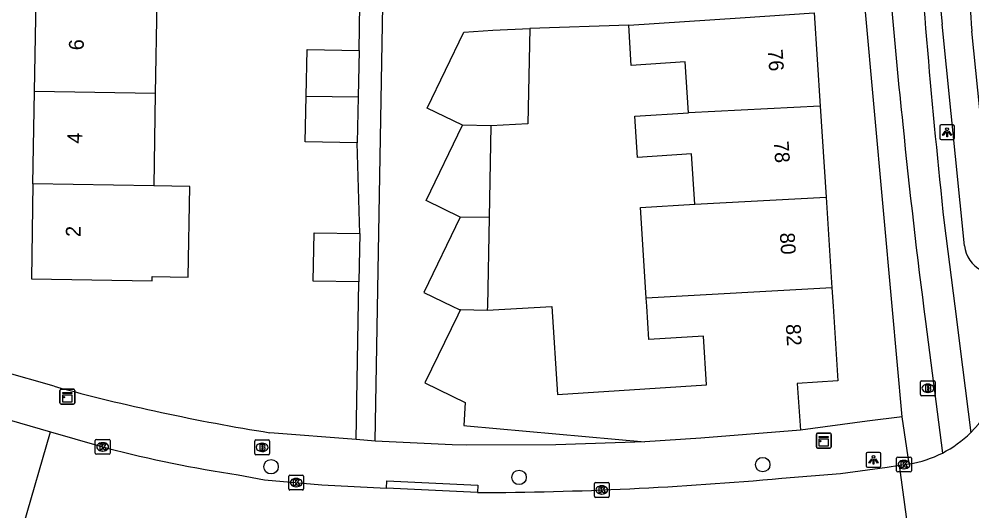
# Model space of a CAD drawing. Extents: x 160026 to 161302, y 384757 to 385701.
# Drawn here: x 160741.7 to 160806.2, y 384986.1 to 385019.4 of the extents above; entities that cross this region are included whole.
import ezdxf

# ---------------------------------------------------------------- set-up
doc = ezdxf.new("R2010")
doc.units = 0
for name, color, linetype in [('IMGEO_Boom', 7, 'Continuous'), ('IMGEO_Brandkraan', 7, 'Continuous'), ('IMGEO_Fietspad_open', 7, 'Continuous'), ('IMGEO_Kast', 7, 'Continuous'), ('IMGEO_Kolk', 7, 'Continuous'), ('IMGEO_Lichtpunt', 7, 'Continuous'), ('IMGEO_Pand', 7, 'Continuous'), ('IMGEO_Pand_nummerreeks', 7, 'Continuous'), ('IMGEO_Parkeervlak_open', 7, 'Continuous'), ('IMGEO_Rijbaan_lokaal_gesloten', 7, 'Continuous'), ('IMGEO_Rijbaan_lokaal_open', 7, 'Continuous'), ('IMGEO_Voetpad_open', 7, 'Continuous')]:
    doc.layers.add(name, color=color, linetype=linetype)

msp = doc.modelspace()

# ---------------------------------------------------------------- linework, layer by layer
at = {"layer": 'IMGEO_Boom'}
for centre in [(160758.765, 384989.14), (160792.032, 384989.282), (160775.542, 384988.414)]:
    msp.add_circle(centre, 0.489, dxfattribs=at)
at = {"layer": 'IMGEO_Brandkraan'}
for p, q in [((160802.703, 384994.017), (160802.703, 384994.869)), ((160802.778, 384994.943), (160803.63, 384994.943)), ((160803.704, 384994.869), (160803.704, 384994.017)), ((160803.214, 384994.163), (160803.189, 384994.163)), ((160803.191, 384994.723), (160803.216, 384994.723)), ((160803.63, 384993.943), (160802.778, 384993.943)), ((160757.734, 384990.949), (160758.586, 384990.949)), ((160757.659, 384990.023), (160757.659, 384990.875)), ((160758.147, 384990.729), (160758.172, 384990.729)), ((160758.66, 384990.875), (160758.66, 384990.023)), ((160758.586, 384989.949), (160757.734, 384989.949)), ((160758.17, 384990.169), (160758.145, 384990.169))]:
    msp.add_line(p, q, dxfattribs=at)
for points in [[(160802.703, 384994.017), (160802.703, 384994.869)], [(160802.778, 384994.943), (160803.63, 384994.943)], [(160803.704, 384994.869), (160803.704, 384994.017)], [(160803.051, 384994.643), (160803.051, 384994.243), (160803.264, 384994.243)], [(160803.282, 384994.643), (160803.051, 384994.643)], [(160803.23, 384994.562), (160803.176, 384994.562), (160803.176, 384994.486)], [(160803.176, 384994.486), (160803.229, 384994.486)], [(160803.238, 384994.41), (160803.176, 384994.41), (160803.176, 384994.329)], [(160803.176, 384994.329), (160803.238, 384994.329)], [(160803.63, 384993.943), (160802.778, 384993.943)], [(160757.734, 384990.949), (160758.586, 384990.949)], [(160757.659, 384990.023), (160757.659, 384990.875)], [(160758.007, 384990.649), (160758.007, 384990.249), (160758.22, 384990.249)], [(160758.238, 384990.649), (160758.007, 384990.649)], [(160758.186, 384990.568), (160758.132, 384990.568), (160758.132, 384990.492)], [(160758.132, 384990.492), (160758.185, 384990.492)], [(160758.194, 384990.416), (160758.132, 384990.416), (160758.132, 384990.335)], [(160758.132, 384990.335), (160758.194, 384990.335)], [(160758.66, 384990.875), (160758.66, 384990.023)], [(160758.586, 384989.949), (160757.734, 384989.949)]]:
    msp.add_lwpolyline(points, dxfattribs=at)
for centre, radius, start, end in [((160802.78, 384994.867), 0.0765, 91.55205, 178.44795), ((160802.78, 384994.867), 0.0765, 91.55205, 178.44795), ((160803.628, 384994.867), 0.0765, 1.55205, 88.44795), ((160803.628, 384994.867), 0.0765, 1.55205, 88.44795), ((160803.231, 384994.524), 0.0379, 267.82845, 90.93552), ((160803.239, 384994.369), 0.0404, 269.87594, 90.50774), ((160803.27, 384994.494), 0.251, 268.66757, 293.53466), ((160803.286, 384994.498), 0.145, 59.4692, 91.53667), ((160803.311, 384994.545), 0.0922, 285.51372, 58.15012), ((160803.316, 384994.353), 0.105, 301.31148, 78.98903), ((160802.78, 384994.019), 0.0765, 181.55205, 268.44795), ((160802.78, 384994.019), 0.0765, 181.55205, 268.44795), ((160803.628, 384994.019), 0.0765, 271.55205, 358.44795), ((160803.628, 384994.019), 0.0765, 271.55205, 358.44795), ((160757.736, 384990.873), 0.0765, 91.55205, 178.44795), ((160757.736, 384990.873), 0.0765, 91.55205, 178.44795), ((160758.584, 384990.873), 0.0765, 1.55205, 88.44795), ((160758.584, 384990.873), 0.0765, 1.55205, 88.44795), ((160758.187, 384990.53), 0.0379, 267.82845, 90.93552), ((160758.195, 384990.375), 0.0404, 269.87594, 90.50774), ((160758.226, 384990.5), 0.251, 268.66757, 293.53466), ((160758.242, 384990.504), 0.145, 59.4692, 91.53667), ((160758.267, 384990.551), 0.0922, 285.51372, 58.15012), ((160758.272, 384990.359), 0.105, 301.31148, 78.98903), ((160757.736, 384990.025), 0.0765, 181.55205, 268.44795), ((160757.736, 384990.025), 0.0765, 181.55205, 268.44795), ((160758.584, 384990.025), 0.0765, 271.55205, 358.44795), ((160758.584, 384990.025), 0.0765, 271.55205, 358.44795)]:
    msp.add_arc(centre, radius, start, end, dxfattribs=at)
for centre, major_axis, ratio, start_param, end_param in [((160803.19, 384994.443), (-0.387, 0.002), 0.722429, 4.712389, 7.853982), ((160803.215, 384994.443), (-0.39, 0.002), 0.717154, 1.570796, 4.712389), ((160758.146, 384990.449), (-0.387, 0.002), 0.722429, 4.712389, 7.853982), ((160758.171, 384990.449), (-0.39, 0.002), 0.717154, 1.570796, 4.712389)]:
    msp.add_ellipse(centre, major_axis=major_axis, ratio=ratio, start_param=start_param, end_param=end_param, dxfattribs=at)
at = {"layer": 'IMGEO_Fietspad_open'}
for points in [[(160804.304, 385005.644), (160804.667, 385002.822), (160805.027, 385000), (160805.547, 384995.863), (160806.104, 384991.441)], [(160803.05, 384998.952), (160804.185, 384990.065)]]:
    msp.add_lwpolyline(points, dxfattribs=at)
for centre, radius, start, end in [((161342.173, 385063.589), 540.981, 183.66637, 186.14879), ((161161.658, 385051.094), 362.235, 183.61885, 186.14936), ((161234.557, 385055.626), 435.213, 185.71448, 187.48234)]:
    msp.add_arc(centre, radius, start, end, dxfattribs=at)
at = {"layer": 'IMGEO_Kast'}
for p, q in [((160744.483, 384993.454), (160744.483, 384994.295)), ((160744.483, 384994.295), (160744.483, 384993.454)), ((160744.558, 384994.379), (160745.399, 384994.379)), ((160745.399, 384994.379), (160744.558, 384994.379)), ((160745.483, 384994.304), (160745.483, 384993.463)), ((160745.483, 384993.463), (160745.483, 384994.304)), ((160745.408, 384993.379), (160744.567, 384993.379)), ((160744.567, 384993.379), (160745.408, 384993.379)), ((160795.658, 384990.476), (160795.658, 384991.317)), ((160795.658, 384991.317), (160795.658, 384990.476)), ((160795.733, 384991.401), (160796.574, 384991.401)), ((160796.574, 384991.401), (160795.733, 384991.401)), ((160796.658, 384991.326), (160796.658, 384990.485)), ((160796.658, 384990.485), (160796.658, 384991.326)), ((160796.583, 384990.401), (160795.742, 384990.401)), ((160795.742, 384990.401), (160796.583, 384990.401))]:
    msp.add_line(p, q, dxfattribs=at)
for points in [[(160744.678, 384994.169), (160745.278, 384994.169), (160745.278, 384994.084), (160744.678, 384994.084), (160744.678, 384994.169)], [(160744.678, 384993.994), (160745.278, 384993.994), (160745.278, 384993.505), (160744.678, 384993.505), (160744.678, 384993.994)], [(160795.853, 384991.191), (160796.453, 384991.191), (160796.453, 384991.106), (160795.853, 384991.106), (160795.853, 384991.191)], [(160795.853, 384991.016), (160796.453, 384991.016), (160796.453, 384990.527), (160795.853, 384990.527), (160795.853, 384991.016)]]:
    msp.add_lwpolyline(points, dxfattribs=at)
for centre in [(160744.762, 384993.843), (160795.937, 384990.865)]:
    msp.add_circle(centre, 0.0377, dxfattribs=at)
for centre, start, end in [((160744.561, 384994.301), 92.4484, 184.28452), ((160744.561, 384994.301), 92.4484, 184.28452), ((160745.405, 384994.301), 2.4484, 94.28452), ((160745.405, 384994.301), 2.4484, 94.28452), ((160745.405, 384993.457), 272.4484, 4.28452), ((160745.405, 384993.457), 272.4484, 4.28452), ((160744.561, 384993.457), 182.4484, 274.28452), ((160744.561, 384993.457), 182.4484, 274.28452), ((160795.736, 384991.323), 92.4484, 184.28452), ((160795.736, 384991.323), 92.4484, 184.28452), ((160796.58, 384991.323), 2.4484, 94.28452), ((160796.58, 384991.323), 2.4484, 94.28452), ((160795.736, 384990.479), 182.4484, 274.28452), ((160795.736, 384990.479), 182.4484, 274.28452), ((160796.58, 384990.479), 272.4484, 4.28452), ((160796.58, 384990.479), 272.4484, 4.28452)]:
    msp.add_arc(centre, 0.0779, start, end, dxfattribs=at)
at = {"layer": 'IMGEO_Kolk'}
for p, q in [((160746.873, 384990.053), (160746.873, 384990.905)), ((160746.948, 384990.979), (160747.8, 384990.979)), ((160747.874, 384990.905), (160747.874, 384990.053)), ((160747.361, 384990.759), (160747.386, 384990.759)), ((160747.8, 384989.979), (160746.948, 384989.979)), ((160747.384, 384990.199), (160747.359, 384990.199)), ((160801.087, 384988.857), (160801.087, 384989.709)), ((160801.162, 384989.783), (160802.014, 384989.783)), ((160802.088, 384989.709), (160802.088, 384988.857)), ((160801.598, 384989.003), (160801.573, 384989.003)), ((160801.575, 384989.563), (160801.6, 384989.563)), ((160759.966, 384987.638), (160759.966, 384988.49)), ((160760.041, 384988.564), (160760.893, 384988.564)), ((160760.454, 384988.344), (160760.479, 384988.344)), ((160760.967, 384988.49), (160760.967, 384987.638)), ((160802.014, 384988.783), (160801.162, 384988.783)), ((160760.477, 384987.784), (160760.452, 384987.784)), ((160780.642, 384987.141), (160780.642, 384987.993)), ((160780.717, 384988.067), (160781.569, 384988.067)), ((160781.13, 384987.847), (160781.155, 384987.847)), ((160781.643, 384987.993), (160781.643, 384987.141)), ((160760.893, 384987.564), (160760.041, 384987.564)), ((160781.569, 384987.067), (160780.717, 384987.067)), ((160781.153, 384987.287), (160781.128, 384987.287))]:
    msp.add_line(p, q, dxfattribs=at)
for points in [[(160746.873, 384990.053), (160746.873, 384990.905)], [(160746.948, 384990.979), (160747.8, 384990.979)], [(160747.874, 384990.905), (160747.874, 384990.053)], [(160747.194, 384990.679), (160747.317, 384990.679), (160747.317, 384990.528), (160747.447, 384990.679), (160747.611, 384990.679), (160747.465, 384990.528), (160747.618, 384990.279), (160747.466, 384990.279), (160747.381, 384990.443), (160747.317, 384990.376), (160747.317, 384990.279), (160747.194, 384990.279), (160747.194, 384990.679)], [(160747.8, 384989.979), (160746.948, 384989.979)], [(160801.087, 384988.857), (160801.087, 384989.709)], [(160801.162, 384989.783), (160802.014, 384989.783)], [(160802.088, 384989.709), (160802.088, 384988.857)], [(160801.408, 384989.483), (160801.531, 384989.483), (160801.531, 384989.332), (160801.661, 384989.483), (160801.825, 384989.483), (160801.679, 384989.332), (160801.832, 384989.083), (160801.68, 384989.083), (160801.595, 384989.247), (160801.531, 384989.18), (160801.531, 384989.083), (160801.408, 384989.083), (160801.408, 384989.483)], [(160759.966, 384987.638), (160759.966, 384988.49)], [(160760.041, 384988.564), (160760.893, 384988.564)], [(160760.967, 384988.49), (160760.967, 384987.638)], [(160802.014, 384988.783), (160801.162, 384988.783)], [(160760.287, 384988.264), (160760.41, 384988.264), (160760.41, 384988.113), (160760.54, 384988.264), (160760.704, 384988.264), (160760.558, 384988.113), (160760.711, 384987.864), (160760.559, 384987.864), (160760.474, 384988.028), (160760.41, 384987.961), (160760.41, 384987.864), (160760.287, 384987.864), (160760.287, 384988.264)], [(160780.642, 384987.141), (160780.642, 384987.993)], [(160780.717, 384988.067), (160781.569, 384988.067)], [(160780.963, 384987.767), (160781.086, 384987.767), (160781.086, 384987.616), (160781.216, 384987.767), (160781.38, 384987.767), (160781.234, 384987.616), (160781.387, 384987.367), (160781.235, 384987.367), (160781.15, 384987.531), (160781.086, 384987.464), (160781.086, 384987.367), (160780.963, 384987.367), (160780.963, 384987.767)], [(160781.643, 384987.993), (160781.643, 384987.141)], [(160760.893, 384987.564), (160760.041, 384987.564)], [(160781.569, 384987.067), (160780.717, 384987.067)]]:
    msp.add_lwpolyline(points, dxfattribs=at)
for centre, start, end in [((160746.95, 384990.903), 91.55205, 178.44795), ((160746.95, 384990.903), 91.55205, 178.44795), ((160747.798, 384990.903), 1.55205, 88.44795), ((160747.798, 384990.903), 1.55205, 88.44795), ((160746.95, 384990.055), 181.55205, 268.44795), ((160746.95, 384990.055), 181.55205, 268.44795), ((160747.798, 384990.055), 271.55205, 358.44795), ((160747.798, 384990.055), 271.55205, 358.44795), ((160801.164, 384989.707), 91.55205, 178.44795), ((160801.164, 384989.707), 91.55205, 178.44795), ((160802.012, 384989.707), 1.55205, 88.44795), ((160802.012, 384989.707), 1.55205, 88.44795), ((160760.043, 384988.488), 91.55205, 178.44795), ((160760.043, 384988.488), 91.55205, 178.44795), ((160760.891, 384988.488), 1.55205, 88.44795), ((160760.891, 384988.488), 1.55205, 88.44795), ((160801.164, 384988.859), 181.55205, 268.44795), ((160801.164, 384988.859), 181.55205, 268.44795), ((160802.012, 384988.859), 271.55205, 358.44795), ((160802.012, 384988.859), 271.55205, 358.44795), ((160780.719, 384987.991), 91.55205, 178.44795), ((160780.719, 384987.991), 91.55205, 178.44795), ((160781.567, 384987.991), 1.55205, 88.44795), ((160781.567, 384987.991), 1.55205, 88.44795), ((160760.043, 384987.64), 181.55205, 268.44795), ((160760.043, 384987.64), 181.55205, 268.44795), ((160760.891, 384987.64), 271.55205, 358.44795), ((160760.891, 384987.64), 271.55205, 358.44795), ((160780.719, 384987.143), 181.55205, 268.44795), ((160780.719, 384987.143), 181.55205, 268.44795), ((160781.567, 384987.143), 271.55205, 358.44795), ((160781.567, 384987.143), 271.55205, 358.44795)]:
    msp.add_arc(centre, 0.0765, start, end, dxfattribs=at)
for centre, major_axis, ratio, start_param, end_param in [((160747.36, 384990.479), (-0.387, 0.002), 0.722429, 4.712389, 7.853982), ((160747.385, 384990.479), (-0.39, 0.002), 0.717154, 1.570796, 4.712389), ((160801.574, 384989.283), (-0.387, 0.002), 0.722429, 4.712389, 7.853982), ((160801.599, 384989.283), (-0.39, 0.002), 0.717154, 1.570796, 4.712389), ((160760.453, 384988.064), (-0.387, 0.002), 0.722429, 4.712389, 7.853982), ((160760.478, 384988.064), (-0.39, 0.002), 0.717154, 1.570796, 4.712389), ((160781.129, 384987.567), (-0.387, 0.002), 0.722429, 4.712389, 7.853982), ((160781.154, 384987.567), (-0.39, 0.002), 0.717154, 1.570796, 4.712389)]:
    msp.add_ellipse(centre, major_axis=major_axis, ratio=ratio, start_param=start_param, end_param=end_param, dxfattribs=at)
at = {"layer": 'IMGEO_Lichtpunt'}
for p, q in [((160804.003, 385012.163), (160804.003, 385011.356)), ((160804.003, 385012.163), (160804.003, 385011.356)), ((160804.905, 385012.258), (160804.097, 385012.258)), ((160804.905, 385012.258), (160804.097, 385012.258)), ((160804.999, 385011.356), (160804.999, 385012.163)), ((160804.999, 385011.356), (160804.999, 385012.163)), ((160804.097, 385011.262), (160804.905, 385011.262)), ((160804.097, 385011.262), (160804.905, 385011.262)), ((160799.028, 384990.009), (160799.028, 384989.202)), ((160799.028, 384990.009), (160799.028, 384989.202)), ((160799.93, 384990.104), (160799.122, 384990.104)), ((160799.93, 384990.104), (160799.122, 384990.104)), ((160800.024, 384989.202), (160800.024, 384990.009)), ((160800.024, 384989.202), (160800.024, 384990.009)), ((160799.122, 384989.108), (160799.93, 384989.108)), ((160799.122, 384989.108), (160799.93, 384989.108))]:
    msp.add_line(p, q, dxfattribs=at)
for points in [[(160804.377, 385011.827), (160804.416, 385011.799), (160804.228, 385011.537), (160804.19, 385011.564), (160804.377, 385011.827)], [(160804.479, 385011.779), (160804.526, 385011.779), (160804.526, 385011.457), (160804.479, 385011.457), (160804.479, 385011.779)], [(160804.589, 385011.799), (160804.627, 385011.826), (160804.814, 385011.564), (160804.775, 385011.536), (160804.589, 385011.799)], [(160799.402, 384989.673), (160799.441, 384989.645), (160799.253, 384989.383), (160799.215, 384989.41), (160799.402, 384989.673)], [(160799.504, 384989.625), (160799.551, 384989.625), (160799.551, 384989.303), (160799.504, 384989.303), (160799.504, 384989.625)], [(160799.614, 384989.645), (160799.652, 384989.672), (160799.839, 384989.41), (160799.8, 384989.382), (160799.614, 384989.645)]]:
    msp.add_lwpolyline(points, dxfattribs=at)
for centre in [(160804.502, 385011.961), (160799.527, 384989.807)]:
    msp.add_circle(centre, 0.0994, dxfattribs=at)
for centre, start, end in [((160804.097, 385012.163), 90, 180), ((160804.097, 385012.163), 90, 180), ((160804.905, 385012.163), 0, 90), ((160804.905, 385012.163), 0, 90), ((160804.097, 385011.356), 180, 270), ((160804.097, 385011.356), 180, 270), ((160804.905, 385011.356), 270, 0), ((160804.905, 385011.356), 270, 360), ((160799.122, 384990.009), 90, 180), ((160799.122, 384990.009), 90, 180), ((160799.93, 384990.009), 0, 90), ((160799.93, 384990.009), 0, 90), ((160799.122, 384989.202), 180, 270), ((160799.122, 384989.202), 180, 270), ((160799.93, 384989.202), 270, 0), ((160799.93, 384989.202), 270, 360)]:
    msp.add_arc(centre, 0.0946, start, end, dxfattribs=at)
at = {"layer": 'IMGEO_Pand'}
for points in [[(160742.758, 385014.51), (160742.862, 385020.749)], [(160751.034, 385020.614), (160750.93, 385014.375)], [(160782.963, 385019.013), (160790.512, 385019.505), (160795.501, 385019.83)], [(160795.501, 385019.83), (160795.911, 385013.53)], [(160771.717, 385012.231), (160769.317, 385013.394), (160771.808, 385018.534), (160773.765, 385018.676), (160776.268, 385018.768)], [(160776.268, 385018.768), (160776.142, 385012.325), (160773.638, 385012.192)], [(160787.013, 385013.079), (160786.789, 385016.521), (160783.14, 385016.283), (160782.963, 385019.013)], [(160761.139, 385014.206), (160761.202, 385017.355), (160764.725, 385017.285)], [(160764.725, 385017.285), (160764.662, 385014.148)], [(160742.655, 385008.271), (160742.758, 385014.51)], [(160750.93, 385014.375), (160742.758, 385014.51)], [(160750.93, 385014.375), (160750.827, 385008.136)], [(160764.6, 385011.036), (160761.077, 385011.106), (160761.139, 385014.206)], [(160761.139, 385014.206), (160764.662, 385014.148)], [(160764.662, 385014.148), (160764.6, 385011.036)], [(160795.911, 385013.53), (160787.013, 385013.079)], [(160795.911, 385013.53), (160796.312, 385007.381)], [(160787.434, 385006.902), (160787.213, 385010.293), (160783.56, 385010.055), (160783.378, 385012.842), (160787.013, 385013.079)], [(160771.558, 385006.023), (160769.25, 385007.142), (160771.717, 385012.231)], [(160773.638, 385012.192), (160771.717, 385012.231)], [(160773.638, 385012.192), (160773.516, 385005.987)], [(160742.655, 385008.271), (160742.548, 385001.845), (160750.72, 385001.709), (160750.725, 385001.994), (160753.166, 385001.953), (160753.268, 385008.096), (160750.827, 385008.136)], [(160750.827, 385008.136), (160742.655, 385008.271)], [(160787.434, 385006.902), (160796.312, 385007.381)], [(160796.312, 385007.381), (160796.713, 385001.232)], [(160784.151, 385000.543), (160783.936, 385003.818), (160783.751, 385006.662), (160787.434, 385006.902)], [(160771.558, 385006.023), (160769.091, 385000.933), (160771.016, 385000), (160771.49, 384999.77), (160771.58, 384999.768)], [(160773.516, 385005.987), (160771.558, 385006.023)], [(160773.516, 385005.987), (160773.399, 385000), (160773.394, 384999.733)], [(160764.712, 385001.637), (160761.614, 385001.695), (160761.675, 385004.962), (160764.773, 385004.904)], [(160764.773, 385004.904), (160764.712, 385001.637)], [(160796.713, 385001.232), (160784.151, 385000.543)], [(160796.713, 385001.232), (160796.793, 385000), (160797.123, 384994.937), (160794.362, 384994.757), (160794.59, 384991.614)], [(160773.394, 384999.733), (160777.756, 384999.964), (160778.143, 384994.022), (160788.236, 384994.679), (160788.022, 384997.975), (160784.334, 384997.734), (160784.186, 385000), (160784.151, 385000.543)], [(160771.58, 384999.768), (160771.399, 384999.396), (160769.162, 384994.809), (160771.905, 384993.477), (160771.799, 384991.924), (160772.022, 384991.904), (160784.052, 384990.825)], [(160771.58, 384999.768), (160773.394, 384999.733)], [(160794.59, 384991.614), (160787.835, 384991.077), (160784.052, 384990.825)]]:
    msp.add_lwpolyline(points, dxfattribs=at)
at = {"layer": 'IMGEO_Parkeervlak_open'}
msp.add_lwpolyline([(160805.674, 385004.084), (160804.172, 385019.069)], dxfattribs=at)
for centre, radius, start, end in [((161062.791, 385042.872), 259.713, 182.1398, 185.25863), ((160807.823, 385004.332), 2.164, 186.59205, 241.83369)]:
    msp.add_arc(centre, radius, start, end, dxfattribs=at)
at = {"layer": 'IMGEO_Rijbaan_lokaal_gesloten'}
for points in [[(160807.953, 385001.077), (160806.186, 385018.591)], [(160743.839, 384991.492), (160747.128, 384990.543), (160747.677, 384990.398)], [(160793.32, 384988.363), (160797.286, 384988.689), (160800.458, 384989.115), (160801.283, 384989.246)], [(160801.283, 384989.246), (160801.944, 384989.326)], [(160802.13, 384983.095), (160801.283, 384989.246)], [(160756.53, 384988.589), (160758.317, 384988.24), (160762.2, 384987.919), (160766.584, 384987.684)], [(160772.723, 384987.388), (160766.584, 384987.684)]]:
    msp.add_lwpolyline(points, dxfattribs=at)
for centre, radius, start, end in [((161181.601, 385051.814), 376.882, 182.66374, 185.05737), ((160800.649, 384997.024), 7.805, 314.33549, 2.32984), ((160800.654, 384997.016), 7.796, 296.93175, 314.35233), ((160768.977, 385072.07), 84.404, 255.3829, 261.51971), ((160800.66, 384996.987), 7.768, 279.51442, 296.98692), ((160771.992, 385220.872), 233.485, 270.17934, 275.24103)]:
    msp.add_arc(centre, radius, start, end, dxfattribs=at)
at = {"layer": 'IMGEO_Rijbaan_lokaal_open'}
for points in [[(160765.809, 384990.866), (160767.813, 385104.916)], [(160782.963, 385019.013), (160776.268, 385018.768)], [(160734.899, 384997.403), (160734.871, 384994.314), (160739.624, 384992.708), (160743.839, 384991.492)], [(160742.018, 384985.19), (160743.839, 384991.492)], [(160784.052, 384990.825), (160778.03, 384990.622), (160772.005, 384990.599), (160771.027, 384990.614), (160765.809, 384990.866)]]:
    msp.add_lwpolyline(points, dxfattribs=at)
at = {"layer": 'IMGEO_Voetpad_open'}
for points in [[(160764.725, 385017.285), (160764.807, 385023.514)], [(160801.456, 384992.515), (160800.781, 385000), (160798.965, 385020.142)], [(160764.773, 385004.904), (160764.6, 385011.036)], [(160764.526, 384990.969), (160764.712, 385001.637)], [(160744.082, 384994.579), (160740.596, 384995.58)], [(160801.456, 384992.515), (160799.089, 384992.223), (160794.59, 384991.614)], [(160801.944, 384989.326), (160801.456, 384992.515)], [(160764.526, 384990.969), (160758.691, 384991.438)], [(160765.809, 384990.866), (160764.526, 384990.969)], [(160766.584, 384987.684), (160766.609, 384988.183), (160772.748, 384987.887), (160772.723, 384987.388)]]:
    msp.add_lwpolyline(points, dxfattribs=at)
msp.add_arc((160780.691, 385129.303), 139.61, 254.79814, 260.93361, dxfattribs=at)

# ---------------------------------------------------------------- texts
at = {"layer": 'IMGEO_Pand_nummerreeks'}
for s, rotation, p in [('6', 89.04912, (160746.086, 385017.3)), ('76', 273.72777, (160792.376, 385017.342)), ('4', 89.04912, (160745.981, 385010.986)), ('78', 273.72777, (160792.781, 385011.139)), ('2', 89.0491, (160745.875, 385004.67)), ('80', 273.72777, (160793.185, 385004.94)), ('82', 273.72402, (160793.587, 384998.764))]:
    msp.add_text(s, height=1, rotation=rotation, dxfattribs=at).set_placement(p)

doc.saveas('drawing.dxf')
